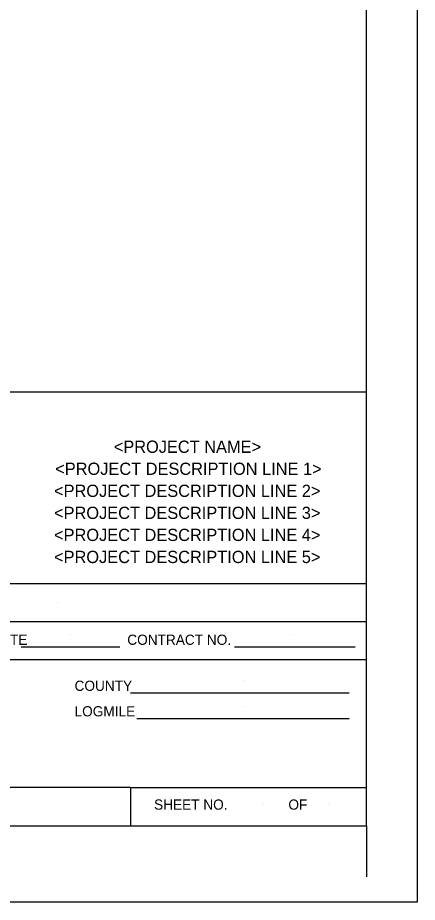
# Model space of a CAD drawing. Extents: x 0 to 34, y 0 to 22.
# Drawn here: x 30.08 to 34, y 0 to 8.67 of the extents above; entities that cross this region are included whole.
import ezdxf

# ---------------------------------------------------------------- set-up
doc = ezdxf.new("R2010")
doc.units = 0
for name, color, linetype in [('BORD-LINE', 7, 'Continuous'), ('CONS-LOGO', 7, 'Continuous'), ('TTLB-TEXT', 7, 'Continuous'), ('USER-LINE', 7, 'Continuous'), ('USER-PAGE', 7, 'Continuous')]:
    doc.layers.add(name, color=color, linetype=linetype)

msp = doc.modelspace()

# ---------------------------------------------------------------- linework, layer by layer
at = {"layer": 'BORD-LINE'}
for p, q in [((33.5, 5), (27.437, 5)), ((33.5, 2.75), (27.437, 2.75)), ((33.5, 2.375), (27.437, 2.375)), ((31.187, 1.125), (27.437, 1.125)), ((31.187, 1.125), (31.187, 0.75)), ((31.187, 1.125), (33.5, 1.125)), ((33.5, 0.75), (33.5, 0.25))]:
    msp.add_line(p, q, dxfattribs=at)
msp.add_lwpolyline([(1.5, 0.75), (33.5, 0.75), (33.5, 21.5), (1.5, 21.5)], close=True, dxfattribs=at)
msp.add_lwpolyline([(27.437, 2.75), (27.437, 3.125), (33.5, 3.125)], dxfattribs=at)
at = {"layer": 'CONS-LOGO'}
msp.add_line((31.7727, 3.925), (31.7727, 3.925), dxfattribs=at)
at = {"layer": 'TTLB-TEXT'}
for p, q in [((30.4684, 2.9375), (30.4684, 2.9375)), ((30.5984, 2.6233), (30.5984, 2.6233)), ((32.7881, 2.6233), (32.7881, 2.6233)), ((30.1154, 2.5034), (31.0814, 2.5034)), ((32.2056, 2.5034), (33.3902, 2.5034)), ((32.3049, 2.1722), (32.3049, 2.1722)), ((31.1881, 2.0523), (33.3306, 2.0523)), ((32.3049, 1.9222), (32.3049, 1.9222)), ((31.2496, 1.8023), (33.3306, 1.8023)), ((32.4956, 0.9579), (32.4956, 0.9579)), ((33.1282, 0.9579), (33.1282, 0.9579))]:
    msp.add_line(p, q, dxfattribs=at)
at = {"layer": 'USER-LINE'}
msp.add_line((34, 0), (34, 0), dxfattribs=at)
at = {"layer": 'USER-PAGE'}
msp.add_lwpolyline([(0, 22), (34, 22), (34, 0), (0, 0)], close=True, dxfattribs=at)

# ---------------------------------------------------------------- texts
at = {"layer": 'TTLB-TEXT'}
for s, height, p in [('<PROJECT NAME>', 0.12, (31.0227, 4.405)), ('<PROJECT DESCRIPTION LINE 1>', 0.12, (30.4487, 4.189)), ('<PROJECT DESCRIPTION LINE 2>', 0.12, (30.4372, 3.973)), ('<PROJECT DESCRIPTION LINE 3>', 0.12, (30.4372, 3.757)), ('<PROJECT DESCRIPTION LINE 4>', 0.12, (30.4372, 3.541)), ('<PROJECT DESCRIPTION LINE 5>', 0.12, (30.4372, 3.325)), ('ADVERTISED DATE', 0.1, (28.9276, 2.5233)), ('CONTRACT NO.', 0.1, (31.1558, 2.5233)), ('COUNTY', 0.1, (30.6384, 2.0722)), ('SHEET NO.', 0.1, (31.418, 0.9079)), ('OF', 0.1, (32.7357, 0.9079))]:
    msp.add_text(s, height=height, dxfattribs=at).set_placement(p)
msp.add_text('LOGMILE           ', height=0.1, rotation=359.99999, dxfattribs=at).set_placement((30.6384, 1.8222))

doc.saveas('drawing.dxf')
